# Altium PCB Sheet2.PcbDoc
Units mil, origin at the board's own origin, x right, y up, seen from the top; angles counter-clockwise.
Board outline 6000 x 4000 mil, 2 copper layers (Top Layer, Bottom Layer); 20 components, 14 nets, 79 pads, 0 vias.
Unrouted connection lines stored in the file: 42.
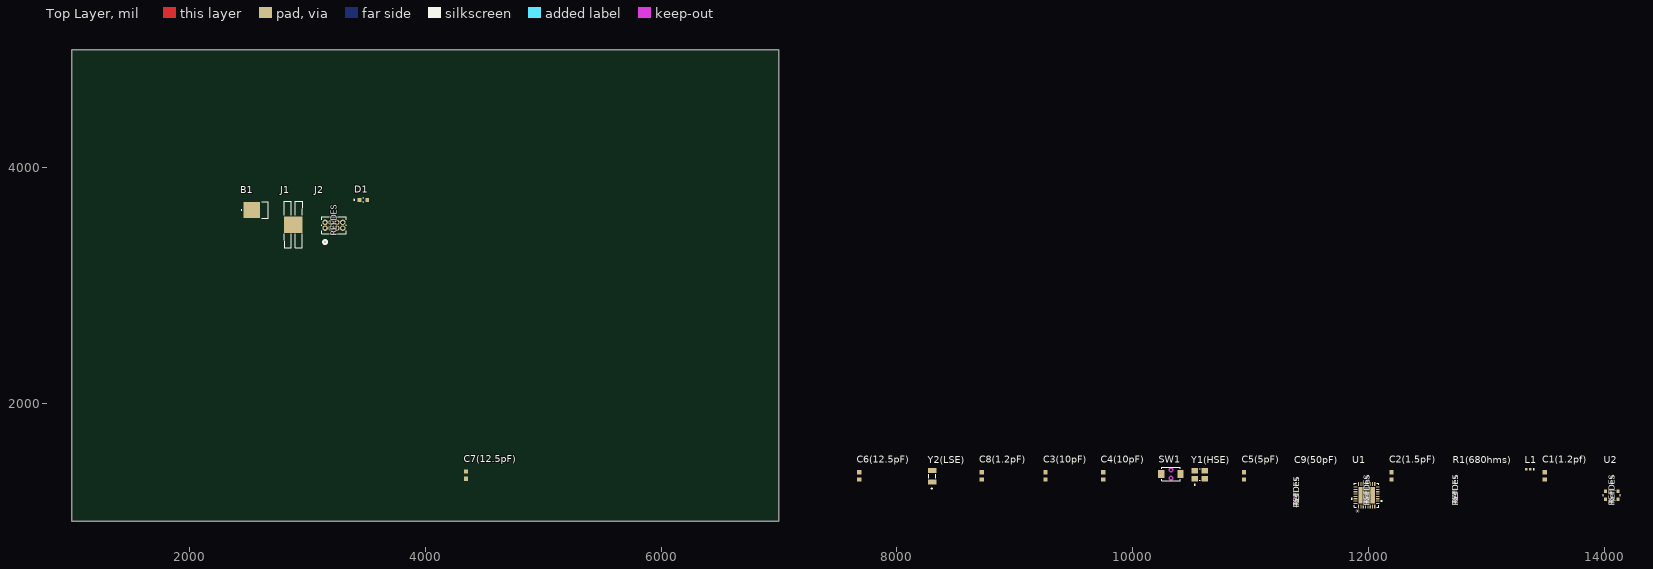
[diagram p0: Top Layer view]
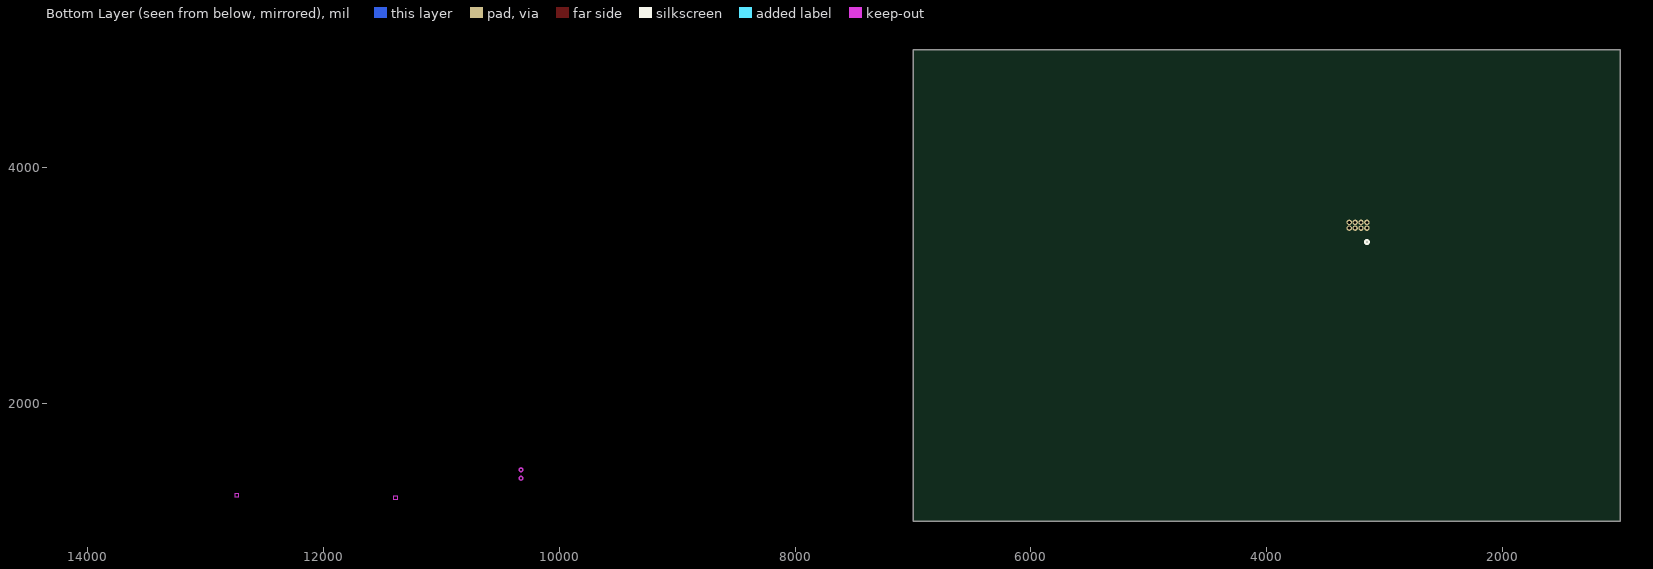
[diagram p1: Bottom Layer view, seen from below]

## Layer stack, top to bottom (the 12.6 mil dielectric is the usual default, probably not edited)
Top Solder: solder mask 0.4, Solder Resist, Dk 3.5
Top Layer: signal copper 1.4
Dielectric 1: dielectric 12.6, FR-4, Dk 4.8
Bottom Layer: signal copper 1.4
Bottom Solder: solder mask 0.4, Solder Resist, Dk 3.5

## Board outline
1000,1000 7000,1000 7000,5000 1000,5000

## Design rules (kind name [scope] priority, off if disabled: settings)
Clearance [All] p1: gap=10 ignorepadtopadclearanceinfootprint=FALSE except(0: Arc-Hole Track-Hole SMDPad-Hole THPad-Hole Via-Hole Fill-Hole Poly-Hole Region-Hole Text-Hole)
PolygonConnect [All] p1: connectstyle=Relief reliefconductorwidth=10 reliefentries=4 polygonreliefangle="90 Angle" airgapwidth=10
RoomDefinition Sheet2 [InComponentClass('Sheet2')] p1: confinementstyle=ConfineIn formatcopy=TRUE lockcomponents=FALSE outline 2410,3270 3540,3270 3540,3860 2410,3860
RoutingVias [All] p1: holewidth=28 width=50 viastyle="Through Hole" minholewidth=28 minwidth=50 maxholewidth=28 maxwidth=50
SolderMaskExpansion [All] p1: expansion=4 istentingtop=FALSE
Width [All] p1: maxlimit=10 minlimit=10 preferedwidth=10
30 further rules are at their usual default settings.

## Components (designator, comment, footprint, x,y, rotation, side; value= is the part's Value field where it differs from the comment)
B1 "110" 110 2565,3640 r0 top
C1(1.2pf) "GRM1885C1H1R5WA01D" CAPC1608X90N 13495,1385 r90 top
C2(1.5pF) "GRM1885C1H1R5WA01D" CAPC1608X90N 12195,1385 r90 top
C3(10pF) "GRM1885C1H100JA01D" CAPC1608X90N 9260,1385 r90 top
C4(10pF) "GRM1885C1H100JA01D" CAPC1608X90N 9750,1385 r90 top
C5(5pF) "GRM1885C1H100JA01D" CAPC1608X90N 10945,1385 r90 top
C6(12.5pF) "GRM1885C1H120JA01D" CAPC1608X90N 7680,1385 r90 top
C7(12.5pF) "GRM1885C1H120JA01D" CAPC1608X90N 4345,1390 r90 top
C8(1.2pF) "GRM1885C1H1R2CA01D" CAPC1608X90N 8720,1385 r90 top
C9(50pF) "06035A500JAT2A" CAP_06033D104JAT2A 11390,1200 r90 top
D1 "LTST-C190KRKT" LEDC1608X35N 3475,3725 r0 top
J1 "112" 112 2880,3515 r90 top
J2 "20021111-00008T4LF" CONN_20021111-00008T4LF_AMP 3150,3485 r90 top
L1 "LQG15HN3N3S02D" INDC1005X55N 13355,1440 r0 top
R1(680hms) "RC0603FR-0768RL" RC0603N_YAG 12735,1220 r90 top
SW1 "GT-TC029B-H040-L1A" SW-SMD_L4.0-W3.0-LS4.8-EH 10325,1400 r0 top
U1 "STM32WB07KCV6TR" VFQFPN-32_STM 11985,1220 r90 top
U2 "2450AT18D0100E" 2450AT18D0100E_JOT 14065,1220 r90 top
Y1(HSE) "ABM8G-16.000MHZ-B4Y-T" XTAL_ABM8G-16.000MHZ-B4Y-T 10570,1395 r90 top
Y2(LSE) "ECS-.327-12.5-34R-TR" XTAL_ECS-.327-12.5-34R-TR 8300,1380 r90 top

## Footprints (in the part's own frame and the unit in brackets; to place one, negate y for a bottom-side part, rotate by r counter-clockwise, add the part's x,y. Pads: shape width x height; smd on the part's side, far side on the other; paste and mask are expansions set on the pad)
110 [mm]
  rect 3.51x3.51 smd: 1(-0.915,0)
  silkscreen extent -3.2,-1.76 2.66,1.76
112 [mm]
  rect 3.56x3.96 smd: 1(0,0)
  silkscreen extent -5,-2 5,2
2450AT18D0100E_JOT [mil]
  rect 28x26 smd paste+0 mask+0: 1(-33.5,53) 2(-33.5,-53) 3(33.5,-53) 4(33.5,53)
  silkscreen extent -40,-72 40,72, body extent -38,-67 38,67, height 51
CAP_06033D104JAT2A [mm]
  rect 0.703x0.96 smd paste+0 mask+0: 1(-0.727,0) 2(0.727,0)
  Top Layer keep-out region: -0.324,-0.429 -0.324,0.429 0.324,0.429 0.324,-0.429
  Keep-Out Layer region: -0.324,-0.48 -0.324,0.48 0.324,0.48 0.324,-0.48
  silkscreen extent -1.99,-0.08 -1.84,0.08, body extent -0.87,-0.48 0.87,0.48, height 0.9
CAPC1608X90N [mm]
  rect 0.89x0.93 smd: 1(-0.77,0) 2(0.77,0)
CONN_20021111-00008T4LF_AMP [mil]
  round 46 / inner round 60 / far side round 46 hole 26 paste-23 mask+0: 1(0,0) 2(50,0) 3(0,-50) 4(50,-50) 5(0,-100) 6(50,-100) 7(0,-150) 8(50,-150)
  silkscreen extent -133,-180 98,30
INDC1005X55N [mm]
  rect 0.54x0.6 smd: 1(-0.432,0) 2(0.432,0)
  silkscreen extent 1.1,-0.1 1.3,0.1, body extent -0.5,-0.25 0.5,0.25, height 0.55
LEDC1608X35N [mm]
  rect 0.81x0.93 smd: A(0.81,0) C(-0.81,0)
  silkscreen extent -2.1,-0.45 0.09,0.45, body extent -0.8,-0.4 0.8,0.4, height 0.8
RC0603N_YAG [mil]
  rect 30x32 smd paste+0 mask+0: 1(-30.5,0) 2(30.5,0)
  Top Layer keep-out region: -13.5,-14 -13.5,14 13.5,14 13.5,-14
  Keep-Out Layer region: -13.5,-16 -13.5,16 13.5,16 13.5,-16
  silkscreen extent -3,-21 3,21, body extent -31,-16 31,16, height 28
SW-SMD_L4.0-W3.0-LS4.8-EH [mm]
  rect 1.35x1.8 smd: 1(-2.075,0) 2(2.075,0)
  Keep-Out Layer board cut-out: 0.4,-0.9 0.36,-1.073 0.249,-1.213 0.089,-1.29 -0.089,-1.29 -0.249,-1.213 -0.36,-1.073 -0.4,-0.9 -0.4,-0.9 -0.36,-0.726 -0.249,-0.587 -0.089,-0.51 0.089,-0.51 0.249,-0.587 0.36,-0.726 0.4,-0.9
  Keep-Out Layer board cut-out: 0.4,0.9 0.36,0.726 0.249,0.587 0.089,0.51 -0.089,0.51 -0.249,0.587 -0.36,0.726 -0.4,0.9 -0.4,0.9 -0.36,1.073 -0.249,1.213 -0.089,1.29 0.089,1.29 0.249,1.213 0.36,1.073 0.4,0.9
  Keep-Out Layer circle w0.005: c0,-0.9 r0.4
  Keep-Out Layer circle w0.005: c0,0.9 r0.4
  Keep-Out Layer region: 0.4,-0.9 0.36,-1.073 0.249,-1.213 0.089,-1.29 -0.089,-1.29 -0.249,-1.213 -0.36,-1.073 -0.4,-0.9 -0.4,-0.9 -0.36,-0.726 -0.249,-0.587 -0.089,-0.51 0.089,-0.51 0.249,-0.587 0.36,-0.726 0.4,-0.9
  Keep-Out Layer region: 0.4,0.9 0.36,0.726 0.249,0.587 0.089,0.51 -0.089,0.51 -0.249,0.587 -0.36,0.726 -0.4,0.9 -0.4,0.9 -0.36,1.073 -0.249,1.213 -0.089,1.29 0.089,1.29 0.249,1.213 0.36,1.073 0.4,0.9
  silkscreen extent -2,-1.5 2,1.5
VFQFPN-32_STM [mil]
  rect 32x10 smd paste+0 mask+0: 1(-94.5,68.9) 2(-94.5,49.21) 3(-94.5,29.53) 4(-94.5,9.84) 5(-94.5,-9.84) 6(-94.5,-29.53) 7(-94.5,-49.21) 8(-94.5,-68.9) 17(94.5,-68.9) 18(94.5,-49.21) 19(94.5,-29.53) 20(94.5,-9.84) 21(94.5,9.84) 22(94.5,29.53) 23(94.5,49.21) 24(94.5,68.9)
  rect 10x32 smd paste+0 mask+0: 9(-68.9,-94.5) 10(-49.21,-94.5) 11(-29.53,-94.5) 12(-9.84,-94.5) 13(9.84,-94.5) 14(29.53,-94.5) 15(49.21,-94.5) 16(68.9,-94.5) 25(68.9,94.5) 26(49.21,94.5) 27(29.53,94.5) 28(9.84,94.5) 29(-9.84,94.5) 30(-29.53,94.5) 31(-49.21,94.5) 32(-68.9,94.5)
  rect 142x142 smd paste+0 mask+0: 33(0,0)
  silkscreen extent -104,-130 130,130, body extent -99,-99 99,99, height 55
XTAL_ABM8G-16.000MHZ-B4Y-T [mm]
  rect 1.2x1.4 smd: 1(-0.85,1.1) 2(-0.85,-1.1) 3(0.85,-1.1) 4(0.85,1.1)
  silkscreen extent -2.3,-0.08 1.25,1.2, body extent -1.6,-1.24 1.6,1.24, height 0.99
XTAL_ECS-.327-12.5-34R-TR [mm]
  rect 1.1x1.9 smd: 1(-1.25,0) 2(1.25,0)
  silkscreen extent -2.7,-0.75 0.44,0.75, body extent -1.6,-0.75 1.6,0.75, height 0.9

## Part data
B1: "Battery Contacts S/M COIN CELL CNCT POSITIVE 16mm UP", Manufacturer_Name="Keystone Electronics", Mouser Part Number=534-110
C1(1.2pf) C2(1.5pF): "CAP 1.5PF 50VDC C0G 0.05PF SMD 0603 PAPER TAPE", Package=None
C3(10pF) C4(10pF) C5(5pF): "SMD Capacitor C0G(EIA) with Capacitance: 10pF Tol. 5%. Rated Voltage: 50Vdc", Package="1608 Murata"
C6(12.5pF) C7(12.5pF): "SMD Capacitor C0G(EIA) with Capacitance: 12pF Tol. 5%. Rated Voltage: 50Vdc", Package="1608 Murata"
C8(1.2pF): "CAP, MLCC, C0G/NP0, 1.2PF, 50V, 0603", Package=None
C9(50pF): "No Description Available", Manufacturer_Name="KYOCERA AVX"
D1: "Red 631nm LED Indication - Discrete 2V 0603 (1608 Metric)", Package="0603 Lite-On"
J1: "Battery Contacts S/M COIN CELL CNCT NEGATIVE 16mm UP", Manufacturer_Name="Keystone Electronics", Mouser Part Number=534-112
J2: "No Description Available", Mfr_Name="Amphenol ICC"
L1: "INDUCTOR, 0402 CASE, 3.3NHÂ±0.3NH; Inductance:3.3nH; Inductance Tolerance:Â± 0.3nH; DC Resistance Max:0.19ohm; DC Current Rating:300mA; Q Factor:8; Self Resonant Frequency:6GHz; Q Test Frequency:100MHz; Core Material:Air; Inductor Case Style:0402; No. of Pins:2; SVHC:No SVHC (19-Dec-2011); DC Current Max:300mA; Inductance Measurement Frequency:100MHz; Inductor Type:Monolithic; Operating Temperature Max:125Â°C; Operating Temperature Min:-55Â°C; Package / Case:0402; Q @ Vr F:8; Q Factor @ Frequency:8 @ 100MHz; Resistance:0.19ohm; Resonant Frequency:6GHz; Tolerance +:9.09%; Tolerance -:9.09%", Package=None
R1(680hms): "No Description Available", Manufacturer_Name=Yageo
SW1: Contact Current=50mA, Insulation Resistance=100MΩ, JLCPCB Part Class="Extended Part", LCSC Part Name=3×4×4两脚立式小龟, Manufacturer=G-Switch(品赞), Operating Force=250gf, Operating Temperature=-40℃~+85℃, Voltage Rating (DC)=12V
U1: "Ultra-low-power, Arm Cortex-M0+ MCU 64 MHz with 256 Kbytes of Flash memory, 64 Kbytes of RAM,  Bluetooth LE 5.4", Manufacturer_Name=STMicroelectronics
U2: "No Description Available", Manufacturer_Name="Johanson Technology"
Y1(HSE): "16 MHz Â±30ppm Kristal 10pF 80 Ohm 4-SMD, KurÅŸunsuz", Package="SMD-4 Abracon"
Y2(LSE): "32.768 kHz Â±20ppm Crystal 12.5pF 50 kOhms 2-SMD, No Lead", Package="ECX-34R-34R-2 ECS"

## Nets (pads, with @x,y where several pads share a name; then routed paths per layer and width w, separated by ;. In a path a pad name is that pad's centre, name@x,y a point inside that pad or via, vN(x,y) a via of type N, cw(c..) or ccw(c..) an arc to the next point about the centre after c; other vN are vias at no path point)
GND: C2(1.5pF).1 C3(10pF).1 C4(10pF).1 C6(12.5pF).1 C7(12.5pF).1 C9(50pF).1 D1.C J1.1 J2.1 J2.2 J2.3 J2.7 SW1.2 U1.23 U2.2 U2.3 U2.4 Y1(HSE).2 Y1(HSE).4
NetC1(1.2pf)_1: C1(1.2pf).1 U1.14
NetC1(1.2pf)_2: C1(1.2pf).2 C2(1.5pF).2 L1.1
NetD1_A: D1.A R1(680hms).2
NetR1(680hms)_1: R1(680hms).1 U1.7
OSC32_IN: C7(12.5pF).2 C8(1.2pF).1 U1.20 Y2(LSE).1
OSC32_OUT: C6(12.5pF).2 C8(1.2pF).2 U1.21 Y2(LSE).2
OSCIN: C3(10pF).2 C5(5pF).1 U1.17 Y1(HSE).1
OSCOUT: C4(10pF).2 C5(5pF).2 U1.16 Y1(HSE).3
PA0: SW1.1 U1.9
RST: J2.4 U1.26
SWCLK: J2.5 U1.11
SWDIO: J2.6 U1.10
VDDSD: B1.1 C9(50pF).2 J2.8 U1.25
pads on no net: L1.2 U1.1 U1.2 U1.3 U1.4 U1.5 U1.6 U1.8 U1.12 U1.13 U1.15 U1.18 U1.19 U1.22 U1.24 U1.27 U1.28 U1.29 U1.30 U1.31 U1.32 U1.33 U2.1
